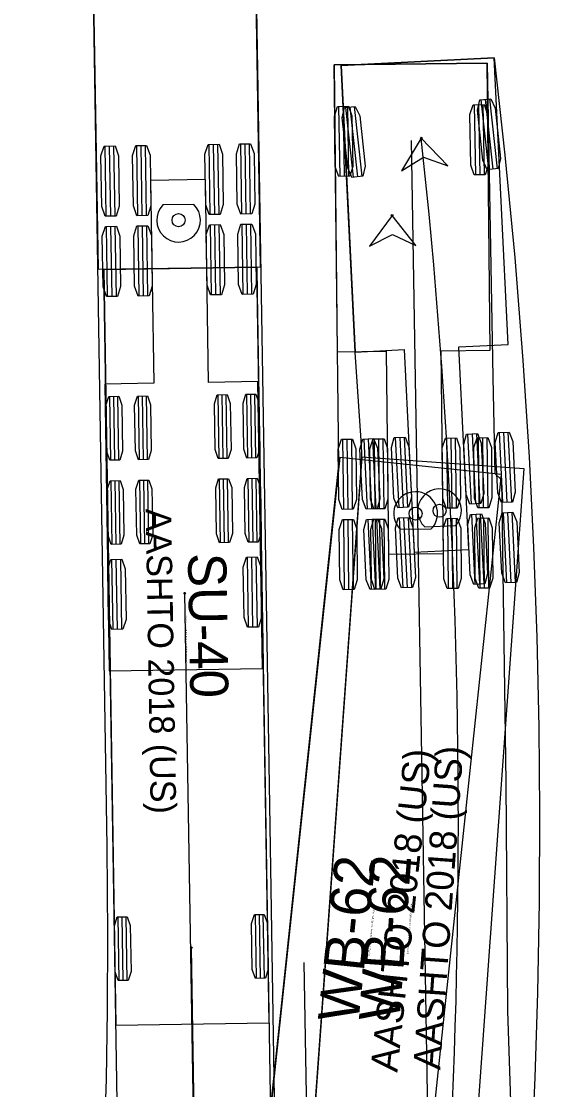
# Model space of a CAD drawing. Extents: x 2297881 to 2300600, y 559917 to 564426.
# Drawn here: x 2299040.7 to 2299067.8, y 562792.5 to 562848.3 of the extents above; entities that cross this region are included whole.
import ezdxf

# ---------------------------------------------------------------- set-up
doc = ezdxf.new("R2010")
doc.units = 0
for name, color, linetype in [('DR_X_Elev_Flow', 7, 'Continuous'), ('PM_P_Channelizing_Line', 7, 'Continuous'), ('PM_P_CL_Double_Solid', 7, 'Continuous'), ('SC_Scratch1', 7, 'Continuous'), ('SN_X_Public', 7, 'Continuous')]:
    doc.layers.add(name, color=color, linetype=linetype)

msp = doc.modelspace()

# ---------------------------------------------------------------- linework, layer by layer
at = {"layer": 'DR_X_Elev_Flow'}
for p, q in [((2299065.414, 562846.416), (2299057.423, 562846.025)), ((2299066.146, 562831.434), (2299065.414, 562846.416)), ((2299057.423, 562846.025), (2299058.156, 562831.043)), ((2299057.423, 562846.025), (2299057.423, 562846.025)), ((2299064.726, 562844.223), (2299065.117, 562840.577)), ((2299064.954, 562844.248), (2299065.344, 562840.602)), ((2299065.182, 562844.272), (2299065.572, 562840.626)), ((2299057.653, 562843.823), (2299058.048, 562840.178)), ((2299057.881, 562843.848), (2299058.276, 562840.203)), ((2299058.109, 562843.873), (2299058.503, 562840.227)), ((2299058.156, 562831.043), (2299060.719, 562831.168)), ((2299060.719, 562831.168), (2299061.237, 562820.581)), ((2299063.582, 562831.308), (2299066.146, 562831.434)), ((2299064.1, 562820.721), (2299063.582, 562831.308)), ((2299064.034, 562826.758), (2299064.213, 562823.096)), ((2299064.263, 562826.77), (2299064.442, 562823.107)), ((2299064.492, 562826.781), (2299064.671, 562823.118)), ((2299065.682, 562826.839), (2299065.861, 562823.177)), ((2299065.911, 562826.85), (2299066.09, 562823.188)), ((2299066.14, 562826.861), (2299066.319, 562823.199)), ((2299058.607, 562826.493), (2299058.787, 562822.831)), ((2299058.836, 562826.504), (2299059.015, 562822.842)), ((2299059.065, 562826.515), (2299059.244, 562822.853)), ((2299060.255, 562826.574), (2299060.435, 562822.911)), ((2299060.484, 562826.585), (2299060.663, 562822.922)), ((2299060.713, 562826.596), (2299060.892, 562822.934)), ((2299058.506, 562825.547), (2299055.06, 562777.671)), ((2299066.984, 562824.937), (2299058.506, 562825.547)), ((2299058.506, 562825.547), (2299058.506, 562825.547)), ((2299063.538, 562777.061), (2299066.984, 562824.937)), ((2299058.813, 562822.298), (2299058.992, 562818.636)), ((2299059.041, 562822.309), (2299059.22, 562818.647)), ((2299059.27, 562822.32), (2299059.449, 562818.658)), ((2299060.461, 562822.379), (2299060.64, 562818.716)), ((2299060.689, 562822.39), (2299060.869, 562818.727)), ((2299060.918, 562822.401), (2299061.097, 562818.739)), ((2299064.239, 562822.563), (2299064.418, 562818.901)), ((2299064.468, 562822.575), (2299064.647, 562818.912)), ((2299064.697, 562822.586), (2299064.876, 562818.923)), ((2299065.887, 562822.644), (2299066.066, 562818.982)), ((2299066.116, 562822.655), (2299066.295, 562818.993)), ((2299066.345, 562822.666), (2299066.524, 562819.004)), ((2299061.798, 562821.902), (2299063.412, 562821.981)), ((2299061.237, 562820.581), (2299064.1, 562820.721))]:
    msp.add_line(p, q, dxfattribs=at)
for points in [[(2299055.249, 562780.343), (2299058.498, 562825.437), (2299058.509, 562825.767), (2299058.47, 562826.426), (2299058.156, 562831.038), (2299057.689, 562840.587), (2299057.423, 562846.025), (2299065.414, 562846.416), (2299065.978, 562841.34), (2299066.492, 562835.977), (2299066.92, 562830.607), (2299067.245, 562825.564), (2299067.481, 562820.852), (2299067.652, 562816.138), (2299067.757, 562811.42), (2299067.796, 562807.037), (2299067.775, 562802.314), (2299067.688, 562797.556), (2299067.547, 562793.128), (2299067.331, 562788.362)], [(2299061.614, 562842.225), (2299060.572, 562840.518), (2299061.72, 562841.231), (2299062.993, 562840.777), (2299061.614, 562842.225)]]:
    msp.add_lwpolyline(points, dxfattribs=at)
for points in [[(2299064.669, 562844.217), (2299065.238, 562844.278), (2299065.464, 562843.786), (2299065.745, 562841.161), (2299065.629, 562840.632), (2299065.06, 562840.571), (2299064.834, 562841.063), (2299064.553, 562843.688)], [(2299057.597, 562843.817), (2299058.165, 562843.879), (2299058.392, 562843.387), (2299058.676, 562840.762), (2299058.56, 562840.233), (2299057.991, 562840.172), (2299057.765, 562840.664), (2299057.481, 562843.288)], [(2299061.614, 562842.225), (2299060.572, 562840.518), (2299061.72, 562841.231), (2299062.993, 562840.777)], [(2299063.978, 562826.756), (2299064.549, 562826.783), (2299064.746, 562826.279), (2299064.875, 562823.642), (2299064.728, 562823.121), (2299064.157, 562823.093), (2299063.959, 562823.598), (2299063.83, 562826.234)], [(2299065.626, 562826.836), (2299066.197, 562826.864), (2299066.394, 562826.36), (2299066.523, 562823.723), (2299066.376, 562823.202), (2299065.805, 562823.174), (2299065.607, 562823.678), (2299065.479, 562826.315)], [(2299058.551, 562826.49), (2299059.122, 562826.518), (2299059.319, 562826.014), (2299059.448, 562823.377), (2299059.301, 562822.856), (2299058.73, 562822.828), (2299058.533, 562823.332), (2299058.404, 562825.969)], [(2299060.199, 562826.571), (2299060.77, 562826.599), (2299060.967, 562826.094), (2299061.096, 562823.458), (2299060.949, 562822.936), (2299060.378, 562822.909), (2299060.181, 562823.413), (2299060.052, 562826.05)], [(2299058.756, 562822.295), (2299059.327, 562822.323), (2299059.524, 562821.819), (2299059.653, 562819.182), (2299059.506, 562818.661), (2299058.935, 562818.633), (2299058.738, 562819.137), (2299058.609, 562821.774)], [(2299060.404, 562822.376), (2299060.975, 562822.404), (2299061.172, 562821.899), (2299061.301, 562819.263), (2299061.154, 562818.741), (2299060.583, 562818.714), (2299060.386, 562819.218), (2299060.257, 562821.855)], [(2299064.183, 562822.561), (2299064.754, 562822.588), (2299064.951, 562822.084), (2299065.08, 562819.447), (2299064.933, 562818.926), (2299064.362, 562818.898), (2299064.164, 562819.403), (2299064.036, 562822.039)], [(2299065.831, 562822.641), (2299066.402, 562822.669), (2299066.599, 562822.165), (2299066.728, 562819.528), (2299066.581, 562819.007), (2299066.01, 562818.979), (2299065.813, 562819.483), (2299065.684, 562822.12)]]:
    msp.add_lwpolyline(points, close=True, dxfattribs=at)
for centre, radius in [((2299061.614, 562842.225), 0.0417), ((2299062.566, 562822.748), 0.34)]:
    msp.add_circle(centre, radius, dxfattribs=at)
for centre, radius, start, end in [((2298726.937, 562806.175), 336.612, 351.67152, 6.14807), ((2299062.566, 562822.748), 1.143, 317.799, 227.799)]:
    msp.add_arc(centre, radius, start, end, dxfattribs=at)
at = {"layer": 'PM_P_Channelizing_Line'}
for p, q in [((2299043.94, 562883.361), (2299044.719, 562835.367)), ((2299053.218, 562835.505), (2299052.438, 562883.499)), ((2299045.153, 562838.141), (2299045.094, 562841.807)), ((2299045.382, 562838.145), (2299045.323, 562841.811)), ((2299045.612, 562838.148), (2299045.552, 562841.815)), ((2299046.803, 562838.168), (2299046.744, 562841.834)), ((2299047.032, 562838.172), (2299046.973, 562841.838)), ((2299047.261, 562838.175), (2299047.202, 562841.841)), ((2299050.586, 562838.229), (2299050.526, 562841.895)), ((2299050.815, 562838.233), (2299050.756, 562841.899)), ((2299051.044, 562838.237), (2299050.985, 562841.903)), ((2299052.236, 562838.256), (2299052.176, 562841.922)), ((2299052.465, 562838.26), (2299052.405, 562841.926)), ((2299052.694, 562838.264), (2299052.634, 562841.93)), ((2299050.327, 562840.059), (2299047.461, 562840.012)), ((2299050.499, 562829.46), (2299050.327, 562840.059)), ((2299047.461, 562840.012), (2299047.633, 562829.413)), ((2299049.723, 562838.757), (2299048.107, 562838.731)), ((2299045.222, 562833.942), (2299045.162, 562837.608)), ((2299045.451, 562833.945), (2299045.391, 562837.611)), ((2299045.68, 562833.949), (2299045.62, 562837.615)), ((2299046.871, 562833.968), (2299046.812, 562837.635)), ((2299047.1, 562833.972), (2299047.041, 562837.638)), ((2299047.33, 562833.976), (2299047.27, 562837.642)), ((2299050.654, 562834.03), (2299050.595, 562837.696)), ((2299050.883, 562834.034), (2299050.824, 562837.7)), ((2299051.112, 562834.037), (2299051.053, 562837.703)), ((2299052.304, 562834.057), (2299052.244, 562837.723)), ((2299052.533, 562834.06), (2299052.474, 562837.727)), ((2299052.762, 562834.064), (2299052.703, 562837.73)), ((2299044.719, 562835.367), (2299053.218, 562835.505)), ((2299053.218, 562835.505), (2299053.218, 562835.505)), ((2299053.066, 562829.502), (2299050.499, 562829.46)), ((2299053.309, 562814.504), (2299053.066, 562829.502)), ((2299047.633, 562829.413), (2299045.067, 562829.372)), ((2299045.067, 562829.372), (2299045.31, 562814.374)), ((2299045.504, 562816.544), (2299045.445, 562820.21)), ((2299045.733, 562816.548), (2299045.674, 562820.214)), ((2299045.962, 562816.551), (2299045.903, 562820.217)), ((2299052.587, 562816.659), (2299052.527, 562820.325)), ((2299052.816, 562816.663), (2299052.756, 562820.329)), ((2299053.045, 562816.666), (2299052.985, 562820.333)), ((2299049.245, 562818.438), (2299050.274, 562755.044)), ((2299045.31, 562814.374), (2299053.309, 562814.504)), ((2299053.309, 562814.504), (2299053.309, 562814.504))]:
    msp.add_line(p, q, dxfattribs=at)
for points in [[(2299040.714, 562758.599), (2299041.233, 562760.776), (2299041.78, 562763.274), (2299042.282, 562765.782), (2299042.742, 562768.299), (2299043.162, 562770.826), (2299043.589, 562773.681), (2299043.927, 562776.229), (2299044.226, 562778.788), (2299044.484, 562781.358), (2299044.703, 562783.938), (2299044.881, 562786.527), (2299045.035, 562789.451), (2299045.16, 562793.039), (2299045.222, 562796.64), (2299045.233, 562800.579), (2299045.197, 562805.181), (2299043.94, 562883.361)], [(2299052.461, 562882.096), (2299053.683, 562807.361), (2299054.3, 562767.973), (2299054.281, 562764.142), (2299054.178, 562761.023), (2299054.34, 562750.972)]]:
    msp.add_lwpolyline(points, dxfattribs=at)
for points in [[(2299045.668, 562838.149), (2299045.097, 562838.14), (2299044.916, 562838.651), (2299044.873, 562841.29), (2299045.037, 562841.806), (2299045.609, 562841.816), (2299045.79, 562841.305), (2299045.832, 562838.665)], [(2299047.318, 562838.176), (2299046.746, 562838.167), (2299046.566, 562838.677), (2299046.523, 562841.317), (2299046.687, 562841.833), (2299047.259, 562841.842), (2299047.439, 562841.332), (2299047.482, 562838.692)], [(2299051.101, 562838.238), (2299050.529, 562838.228), (2299050.349, 562838.739), (2299050.306, 562841.378), (2299050.47, 562841.895), (2299051.042, 562841.904), (2299051.222, 562841.393), (2299051.265, 562838.754)], [(2299052.751, 562838.264), (2299052.179, 562838.255), (2299051.998, 562838.766), (2299051.955, 562841.405), (2299052.119, 562841.921), (2299052.691, 562841.931), (2299052.872, 562841.42), (2299052.915, 562838.78)], [(2299045.737, 562833.95), (2299045.165, 562833.941), (2299044.984, 562834.451), (2299044.941, 562837.091), (2299045.105, 562837.607), (2299045.677, 562837.616), (2299045.858, 562837.106), (2299045.901, 562834.466)], [(2299047.386, 562833.977), (2299046.815, 562833.967), (2299046.634, 562834.478), (2299046.591, 562837.118), (2299046.755, 562837.634), (2299047.327, 562837.643), (2299047.508, 562837.132), (2299047.55, 562834.493)], [(2299051.169, 562834.038), (2299050.597, 562834.029), (2299050.417, 562834.539), (2299050.374, 562837.179), (2299050.538, 562837.695), (2299051.11, 562837.704), (2299051.29, 562837.194), (2299051.333, 562834.554)], [(2299052.819, 562834.065), (2299052.247, 562834.056), (2299052.066, 562834.566), (2299052.024, 562837.206), (2299052.188, 562837.722), (2299052.76, 562837.731), (2299052.94, 562837.221), (2299052.983, 562834.581)], [(2299046.019, 562816.552), (2299045.447, 562816.543), (2299045.267, 562817.053), (2299045.224, 562819.693), (2299045.388, 562820.209), (2299045.96, 562820.218), (2299046.14, 562819.708), (2299046.183, 562817.068)], [(2299053.102, 562816.667), (2299052.53, 562816.658), (2299052.349, 562817.168), (2299052.306, 562819.808), (2299052.47, 562820.324), (2299053.042, 562820.333), (2299053.223, 562819.823), (2299053.266, 562817.183)]]:
    msp.add_lwpolyline(points, close=True, dxfattribs=at)
for centre, radius in [((2299048.928, 562837.936), 0.34), ((2299049.245, 562818.438), 0.0417)]:
    msp.add_circle(centre, radius, dxfattribs=at)
msp.add_arc((2299048.928, 562837.936), 1.143, 135.9306, 45.9306, dxfattribs=at)
at = {"layer": 'PM_P_CL_Double_Solid'}
for p, q in [((2299065.051, 562846.142), (2299057.051, 562846.052)), ((2299057.051, 562846.052), (2299057.219, 562831.053)), ((2299057.051, 562846.052), (2299057.051, 562846.052)), ((2299065.218, 562831.143), (2299065.051, 562846.142)), ((2299064.377, 562843.969), (2299064.439, 562840.302)), ((2299064.606, 562843.972), (2299064.668, 562840.306)), ((2299064.836, 562843.976), (2299064.897, 562840.31)), ((2299057.294, 562843.884), (2299057.356, 562840.218)), ((2299057.524, 562843.888), (2299057.585, 562840.222)), ((2299057.753, 562843.892), (2299057.814, 562840.226)), ((2299062.292, 562770.661), (2299061.096, 562842.097)), ((2299062.652, 562831.114), (2299065.218, 562831.143)), ((2299062.77, 562820.515), (2299062.652, 562831.114)), ((2299057.219, 562831.053), (2299059.785, 562831.082)), ((2299059.785, 562831.082), (2299059.904, 562820.483)), ((2299057.499, 562826.489), (2299057.54, 562822.823)), ((2299057.728, 562826.492), (2299057.769, 562822.826)), ((2299057.957, 562826.495), (2299057.998, 562822.828)), ((2299059.149, 562826.508), (2299059.19, 562822.841)), ((2299059.378, 562826.51), (2299059.419, 562822.844)), ((2299059.607, 562826.513), (2299059.648, 562822.847)), ((2299062.932, 562826.55), (2299062.973, 562822.884)), ((2299063.161, 562826.553), (2299063.202, 562822.886)), ((2299063.39, 562826.555), (2299063.431, 562822.889)), ((2299064.582, 562826.569), (2299064.623, 562822.902)), ((2299064.811, 562826.571), (2299064.852, 562822.905)), ((2299065.04, 562826.574), (2299065.081, 562822.907)), ((2299057.351, 562825.532), (2299052.292, 562777.8)), ((2299065.804, 562824.637), (2299057.351, 562825.532)), ((2299057.351, 562825.532), (2299057.351, 562825.532)), ((2299060.745, 562776.904), (2299065.804, 562824.637)), ((2299057.546, 562822.29), (2299057.587, 562818.623)), ((2299057.775, 562822.292), (2299057.816, 562818.626)), ((2299058.004, 562822.295), (2299058.045, 562818.628)), ((2299059.196, 562822.308), (2299059.237, 562818.642)), ((2299059.425, 562822.311), (2299059.466, 562818.644)), ((2299059.654, 562822.313), (2299059.695, 562818.647)), ((2299062.979, 562822.35), (2299063.02, 562818.684)), ((2299063.208, 562822.353), (2299063.249, 562818.687)), ((2299063.437, 562822.356), (2299063.478, 562818.689)), ((2299064.629, 562822.369), (2299064.67, 562818.702)), ((2299064.858, 562822.371), (2299064.899, 562818.705)), ((2299065.087, 562822.374), (2299065.128, 562818.708)), ((2299060.515, 562821.781), (2299062.131, 562821.799)), ((2299059.904, 562820.483), (2299062.77, 562820.515))]:
    msp.add_line(p, q, dxfattribs=at)
for points in [[(2299052.657, 562781.244), (2299057.275, 562824.816), (2299057.296, 562825.147), (2299057.051, 562846.052), (2299065.051, 562846.142), (2299065.354, 562829.726), (2299065.453, 562824.701), (2299065.808, 562824.361), (2299066.036, 562808.569), (2299066.122, 562796.607), (2299066.526, 562784.544)], [(2299060.088, 562838.186), (2299058.898, 562836.58), (2299060.105, 562837.187), (2299061.332, 562836.62), (2299060.088, 562838.186)]]:
    msp.add_lwpolyline(points, dxfattribs=at)
for points in [[(2299064.32, 562843.968), (2299064.892, 562843.977), (2299065.073, 562843.467), (2299065.117, 562840.827), (2299064.954, 562840.311), (2299064.382, 562840.302), (2299064.201, 562840.812), (2299064.157, 562843.452)], [(2299057.238, 562843.883), (2299057.81, 562843.893), (2299057.99, 562843.383), (2299058.035, 562840.743), (2299057.871, 562840.227), (2299057.299, 562840.217), (2299057.118, 562840.728), (2299057.074, 562843.367)], [(2299060.088, 562838.186), (2299058.898, 562836.58), (2299060.105, 562837.187), (2299061.332, 562836.62)], [(2299057.442, 562826.489), (2299058.014, 562826.495), (2299058.192, 562825.984), (2299058.222, 562823.344), (2299058.055, 562822.829), (2299057.483, 562822.822), (2299057.305, 562823.334), (2299057.276, 562825.974)], [(2299059.092, 562826.507), (2299059.664, 562826.514), (2299059.842, 562826.002), (2299059.872, 562823.362), (2299059.705, 562822.847), (2299059.133, 562822.841), (2299058.955, 562823.352), (2299058.926, 562825.992)], [(2299062.875, 562826.55), (2299063.447, 562826.556), (2299063.625, 562826.045), (2299063.655, 562823.405), (2299063.488, 562822.889), (2299062.916, 562822.883), (2299062.738, 562823.394), (2299062.709, 562826.034)], [(2299064.525, 562826.568), (2299065.097, 562826.574), (2299065.275, 562826.063), (2299065.305, 562823.423), (2299065.138, 562822.908), (2299064.566, 562822.902), (2299064.388, 562823.413), (2299064.359, 562826.053)], [(2299057.489, 562822.289), (2299058.061, 562822.295), (2299058.239, 562821.784), (2299058.269, 562819.144), (2299058.102, 562818.629), (2299057.53, 562818.623), (2299057.352, 562819.134), (2299057.323, 562821.774)], [(2299059.139, 562822.307), (2299059.711, 562822.314), (2299059.889, 562821.802), (2299059.919, 562819.163), (2299059.752, 562818.647), (2299059.18, 562818.641), (2299059.002, 562819.152), (2299058.973, 562821.792)], [(2299062.922, 562822.35), (2299063.494, 562822.356), (2299063.672, 562821.845), (2299063.702, 562819.205), (2299063.535, 562818.69), (2299062.963, 562818.683), (2299062.785, 562819.195), (2299062.756, 562821.835)], [(2299064.572, 562822.368), (2299065.144, 562822.375), (2299065.322, 562821.863), (2299065.352, 562819.223), (2299065.185, 562818.708), (2299064.613, 562818.702), (2299064.435, 562819.213), (2299064.406, 562821.853)]]:
    msp.add_lwpolyline(points, close=True, dxfattribs=at)
for centre, radius in [((2299060.088, 562838.186), 0.0417), ((2299061.314, 562822.598), 0.34)]:
    msp.add_circle(centre, radius, dxfattribs=at)
msp.add_arc((2299061.314, 562822.598), 1.143, 315.6406, 225.6406, dxfattribs=at)
at = {"layer": 'SC_Scratch1'}
msp.add_line((2299055.962, 562770.312), (2299055.494, 562799.14), dxfattribs=at)
at = {"layer": 'SN_X_Public'}
for p, q in [((2299053.016, 562835.48), (2299045.017, 562835.35)), ((2299045.017, 562835.35), (2299045.658, 562795.855)), ((2299053.657, 562795.985), (2299053.016, 562835.48)), ((2299045.387, 562825.388), (2299045.333, 562828.721)), ((2299045.595, 562825.391), (2299045.541, 562828.724)), ((2299045.804, 562825.395), (2299045.749, 562828.728)), ((2299046.887, 562825.412), (2299046.833, 562828.745)), ((2299047.095, 562825.416), (2299047.041, 562828.749)), ((2299047.303, 562825.419), (2299047.249, 562828.752)), ((2299051.053, 562825.48), (2299050.999, 562828.813)), ((2299051.261, 562825.483), (2299051.207, 562828.816)), ((2299051.469, 562825.487), (2299051.415, 562828.82)), ((2299052.553, 562825.504), (2299052.498, 562828.837)), ((2299052.761, 562825.508), (2299052.707, 562828.841)), ((2299052.969, 562825.511), (2299052.915, 562828.844)), ((2299051.124, 562821.081), (2299051.07, 562824.414)), ((2299051.333, 562821.084), (2299051.278, 562824.417)), ((2299051.541, 562821.087), (2299051.487, 562824.42)), ((2299052.624, 562821.105), (2299052.57, 562824.438)), ((2299052.832, 562821.108), (2299052.778, 562824.441)), ((2299053.041, 562821.112), (2299052.987, 562824.445)), ((2299045.458, 562820.989), (2299045.404, 562824.322)), ((2299045.667, 562820.992), (2299045.613, 562824.325)), ((2299045.875, 562820.995), (2299045.821, 562824.328)), ((2299046.958, 562821.013), (2299046.904, 562824.346)), ((2299047.166, 562821.016), (2299047.112, 562824.349)), ((2299047.375, 562821.02), (2299047.321, 562824.353)), ((2299045.829, 562798.192), (2299045.775, 562801.525)), ((2299046.037, 562798.195), (2299045.983, 562801.528)), ((2299046.245, 562798.198), (2299046.191, 562801.531)), ((2299052.994, 562798.308), (2299052.94, 562801.641)), ((2299053.203, 562798.311), (2299053.149, 562801.644)), ((2299053.411, 562798.315), (2299053.357, 562801.648)), ((2299049.593, 562799.92), (2299050.353, 562753.138)), ((2299045.658, 562795.855), (2299053.657, 562795.985)), ((2299053.657, 562795.985), (2299053.657, 562795.985))]:
    msp.add_line(p, q, dxfattribs=at)
for points in [[(2299045.326, 562759.946), (2299045.669, 562763.147), (2299045.794, 562764.758), (2299045.887, 562766.377), (2299045.96, 562768.327), (2299046.002, 562770.611), (2299045.986, 562775.52), (2299045.017, 562835.35), (2299053.016, 562835.48), (2299053.039, 562834.065)], [(2299053.039, 562834.065), (2299053.792, 562787.911), (2299053.98, 562783.14), (2299054.502, 562773.87), (2299054.564, 562771.476), (2299054.549, 562769.439), (2299054.479, 562767.416), (2299054.357, 562765.405), (2299054.19, 562763.406), (2299054.418, 562749.071)]]:
    msp.add_lwpolyline(points, dxfattribs=at)
for points in [[(2299045.855, 562825.396), (2299045.335, 562825.387), (2299045.171, 562825.851), (2299045.132, 562828.251), (2299045.281, 562828.72), (2299045.801, 562828.729), (2299045.965, 562828.264), (2299046.004, 562825.865)], [(2299047.355, 562825.42), (2299046.835, 562825.412), (2299046.671, 562825.876), (2299046.632, 562828.275), (2299046.781, 562828.744), (2299047.301, 562828.753), (2299047.465, 562828.289), (2299047.504, 562825.889)], [(2299051.521, 562825.488), (2299051.001, 562825.479), (2299050.837, 562825.943), (2299050.798, 562828.343), (2299050.947, 562828.812), (2299051.467, 562828.821), (2299051.631, 562828.357), (2299051.67, 562825.957)], [(2299053.021, 562825.512), (2299052.501, 562825.504), (2299052.337, 562825.968), (2299052.298, 562828.367), (2299052.447, 562828.836), (2299052.967, 562828.845), (2299053.131, 562828.381), (2299053.17, 562825.981)], [(2299051.593, 562821.088), (2299051.073, 562821.08), (2299050.908, 562821.544), (2299050.869, 562823.944), (2299051.018, 562824.413), (2299051.538, 562824.421), (2299051.703, 562823.957), (2299051.742, 562821.557)], [(2299053.092, 562821.113), (2299052.572, 562821.104), (2299052.408, 562821.568), (2299052.369, 562823.968), (2299052.518, 562824.437), (2299053.038, 562824.446), (2299053.202, 562823.981), (2299053.241, 562821.582)], [(2299045.927, 562820.996), (2299045.407, 562820.988), (2299045.242, 562821.452), (2299045.203, 562823.852), (2299045.353, 562824.321), (2299045.872, 562824.329), (2299046.037, 562823.865), (2299046.076, 562821.465)], [(2299047.426, 562821.021), (2299046.906, 562821.012), (2299046.742, 562821.476), (2299046.703, 562823.876), (2299046.852, 562824.345), (2299047.372, 562824.353), (2299047.537, 562823.889), (2299047.575, 562821.49)], [(2299046.297, 562798.199), (2299045.777, 562798.191), (2299045.613, 562798.655), (2299045.574, 562801.055), (2299045.723, 562801.524), (2299046.243, 562801.532), (2299046.407, 562801.068), (2299046.446, 562798.668)], [(2299053.463, 562798.316), (2299052.943, 562798.307), (2299052.778, 562798.771), (2299052.74, 562801.171), (2299052.889, 562801.64), (2299053.409, 562801.649), (2299053.573, 562801.184), (2299053.612, 562798.785)]]:
    msp.add_lwpolyline(points, close=True, dxfattribs=at)
msp.add_circle((2299049.593, 562799.92), 0.0417, dxfattribs=at)

# ---------------------------------------------------------------- texts
at = {"layer": 'DR_X_Elev_Flow'}
for s, height, p in [('AASHTO 2018 (US)', 1.41667, (2299062.599, 562793.506)), ('WB-62', 2.125, (2299060.471, 562796.017)), ('(c) 2021 Transoft Solutions, Inc. All rights reserved.', 0.085, (2299060.94, 562799.573))]:
    msp.add_text(s, height=height, rotation=85.883, dxfattribs=at).set_placement(p)
at = {"layer": 'PM_P_CL_Double_Solid'}
for s, height, p in [('AASHTO 2018 (US)', 1.41667, (2299060.36, 562793.371)), ('WB-62', 2.125, (2299058.319, 562795.953)), ('(c) 2021 Transoft Solutions, Inc. All rights reserved.', 0.085, (2299058.908, 562799.491))]:
    msp.add_text(s, height=height, rotation=83.9507, dxfattribs=at).set_placement(p)
at = {"layer": 'SN_X_Public'}
for s, height, p in [('AASHTO 2018 (US)', 1.33333, (2299047.213, 562822.848)), ('SU-40', 2, (2299049.418, 562820.527)), ('(c) 2021 Transoft Solutions, Inc. All rights reserved.', 0.08, (2299049.27, 562817.297))]:
    msp.add_text(s, height=height, rotation=270.9306, dxfattribs=at).set_placement(p)

doc.saveas('drawing.dxf')
